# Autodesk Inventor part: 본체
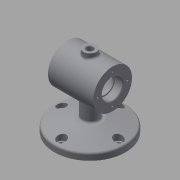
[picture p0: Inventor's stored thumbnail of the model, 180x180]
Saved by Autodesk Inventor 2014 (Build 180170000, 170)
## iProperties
Created: 2018-12
Part Number: 본체
Material: Generic
Document SubType Name: Modeling
Designer: kh
Density: 1 g/cm^3
Appearance: Default
Author: kh
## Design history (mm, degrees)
sketch "Sketch1"
  geometry: C1 r 55 at (0, 0); 1 further point
  constraints: 1 centre point, 1 coincident
  dimensions: "d0" = 110 diameter of C1
extrude "Extrusion1" new body sketch "Sketch1" distance "d1" = 10; taper "d2" = 0 deg
sketch "Sketch2"
  geometry: L1 (0, 0)-(0, 75); L2 (35, 75)-(-35, 75); L3 (-35, 91)-(-23, 91); L4 (-23, 91)-(-23, 89); L5 (-23, 89)-(-20, 89); L6 (-20, 89)-(-20, 100); L7 (-20, 100)-(20, 100); L8 (20, 100)-(20, 89); L9 (20, 89)-(23, 89); L10 (23, 89)-(23, 91); L11 (23, 91)-(35, 91); L12 (35, 91)-(35, 105); L13 (35, 105)-(-35, 105); L14 (-35, 105)-(-35, 91)
  constraints: 28 end point, 10 parallel, 2 perpendicular, 1 collinear, 1 midpoint, 1 vertical, 1 vertical alignment
  dimensions: "d3" = 75 distance of L1.end L1.start; "d4" = 70 distance of L2.start L2.end; "d5" = 12 distance of L3.start L3.end; "d6" = 3 distance of L4.end L5.end; "d7" = 40 distance of L6.end L7.end; "d8" = 3 distance of L8.end L9.end; "d9" = 12 distance of L10.end L11.end; "d10" = 32 diameter of L3 L2; "d11" = 28 diameter of L5 L2; "d12" = 50 diameter of L7 L2; "d13" = 28 diameter of L9 L2; "d14" = 32 diameter of L11 L2; "d15" = 60 diameter of L13 L2
revolve "Revolution1" sketch "Sketch2" stored, may be unused: angle "d16" = 90 deg
sketch "Sketch3"
  geometry: C1 r 12 at (0, 0); 1 further point
  constraints: 1 centre point, 1 coincident
  dimensions: "d17" = 24 diameter of C1
extrude "Extrusion2" join sketch "Sketch3" stored distance "d18" = 10; taper "d19" = 0 deg
sketch "Sketch4"
  geometry: L1 (55, 10)-(-55, 10) reference; L2 (-55, 0)-(55, 0) reference; L3 (-12, 10)-(-12, 45) reference; L4 (-55, 0)-(-55, 10) reference; L5 (-55, 10)-(-12, 21.522); L6 (12, 10)-(12, 45) reference; L7 (-12, 21.522)-(12, 21.522); 1 further point
  constraints: 4 end point, 2 point on line, 1 perpendicular
  dimensions: "d20" = 75 deg angle of L5 L4
  node "Projected Loop1"
workplane "Work Plane1"
sketch "Sketch5"
  geometry: C1 r 10 at (0, 0); 1 further point
  constraints: 1 centre point, 1 coincident
  dimensions: "d22" = 20 diameter of C1
extrude "Extrusion3" join sketch "Sketch5" stored distance "d23" = 10; taper "d24" = 0 deg
hole "Hole1" diameter "d27" = 10; stored, may be unused: countersink angle "d31" = 90 deg, drill point angle "d33" = 118 deg; dims "d25" = 10, "d26" = 10, "d28" = 6, "d29" = 4, "d30" = 2, "d32" = 8
fillet "Fillet1" dims "d34" = 3
fillet "Fillet2" dims "d35" = 0.3
chamfer "Chamfer1" distance "d36" = 1; stored, may be unused: second distance "d37" = 2, angle "d38" = 45 deg
sketch "Sketch6" dims "d39" = 46
  geometry: L1 (0, 0)-(23, 0); C1 r 17 at (0, 0) reference; 2 further points
  constraints: 2 coincident, 2 end point, 1 horizontal, 1 horizontal alignment, 2 other
hole "Hole2" sketch "Sketch6" at (23, 0) diameter "d40" = 3.459; stored, may be unused: countersink angle "d44" = 90 deg, drill point angle "d46" = 118 deg; dims "d41" = 8, "d42" = 4, "d43" = 2, "d45" = 10
pattern_circular "Circular Pattern1" dims angle "d48" = 360 deg
mirror "Mirror1"
workplane "Work Plane2"
sketch "Sketch7" dims "d1" = 10
  geometry: L1 (-35, 30)-(35, 30) reference; L2 (-35, -30)-(-35, 30) reference; L3 (-22.743, 3.292)-(22.743, 3.292); L4 (22.743, 3.292)-(22.743, -3.292); L5 (22.743, -3.292)-(-22.743, -3.292); L6 (-22.743, -3.292)-(-22.743, 3.292); L7 (-22.743, 3.292)-(22.743, -3.292); L8 (0, 30)-(0, 0); 1 further point
  constraints: 4 end point, 2 midpoint, 1 parallel, 2 other
  dimensions: "d50" = 30 distance of L8.end L8.start; "d51" = 35 distance between parallel lines of L8 L2
emboss "Emboss1" sketch "Sketch7" dims "d52" = 0.5, "d53" = 0
workplane "Work Plane3"
sketch "Sketch8"
  geometry: C1 r 12 at (-12, 0) reference; 1 further point
sketch "Sketch9"
  geometry: C1 r 55 at (0, 0) reference; C2 r 55 at (0, 0); 1 further point
  constraints: 1 centre point, 1 coincident, 1 concentric
extrude "Extrusion4" join sketch "Sketch9" distance "d54" = 10; taper "d55" = -75 deg
fillet "Fillet3" dims "d56" = 3
sketch "Sketch10" dims "d57" = 88
  geometry: L1 (0, 0)-(0, -44); C1 r 4.5 at (0, -44); 1 further point
  constraints: 2 coincident, 2 end point, 1 centre point, 1 vertical, 1 vertical alignment, 2 other
  dimensions: "d58" = 9 diameter of C1
extrude "Extrusion5" cut sketch "Sketch10" distance "d59" = 10; taper "d60" = 0 deg
workplane "Work Plane4"
sketch "Sketch11"
  geometry: C1 r 4.5 at (0, -44) reference; C2 r 7 at (0, -44); 1 further point
  constraints: 1 centre point, 1 coincident
  dimensions: "d61" = 14 diameter of C2
extrude "Extrusion6" cut sketch "Sketch11" stored distance "d62" = 10; taper "d63" = 0 deg
pattern_circular "Circular Pattern2" dims angle "d65" = 360 deg
fillet "Fillet4" dims "d67" = 3
fillet "Fillet5" dims "d68" = 3
chamfer "Chamfer2" distance "d69" = 1; stored, may be unused: second distance "d70" = 2, angle "d71" = 45 deg
fillet "Fillet6" dims "d72" = 3
body "Solid1"
node "Projected Loop2"
other parameters: "d21" = 112
